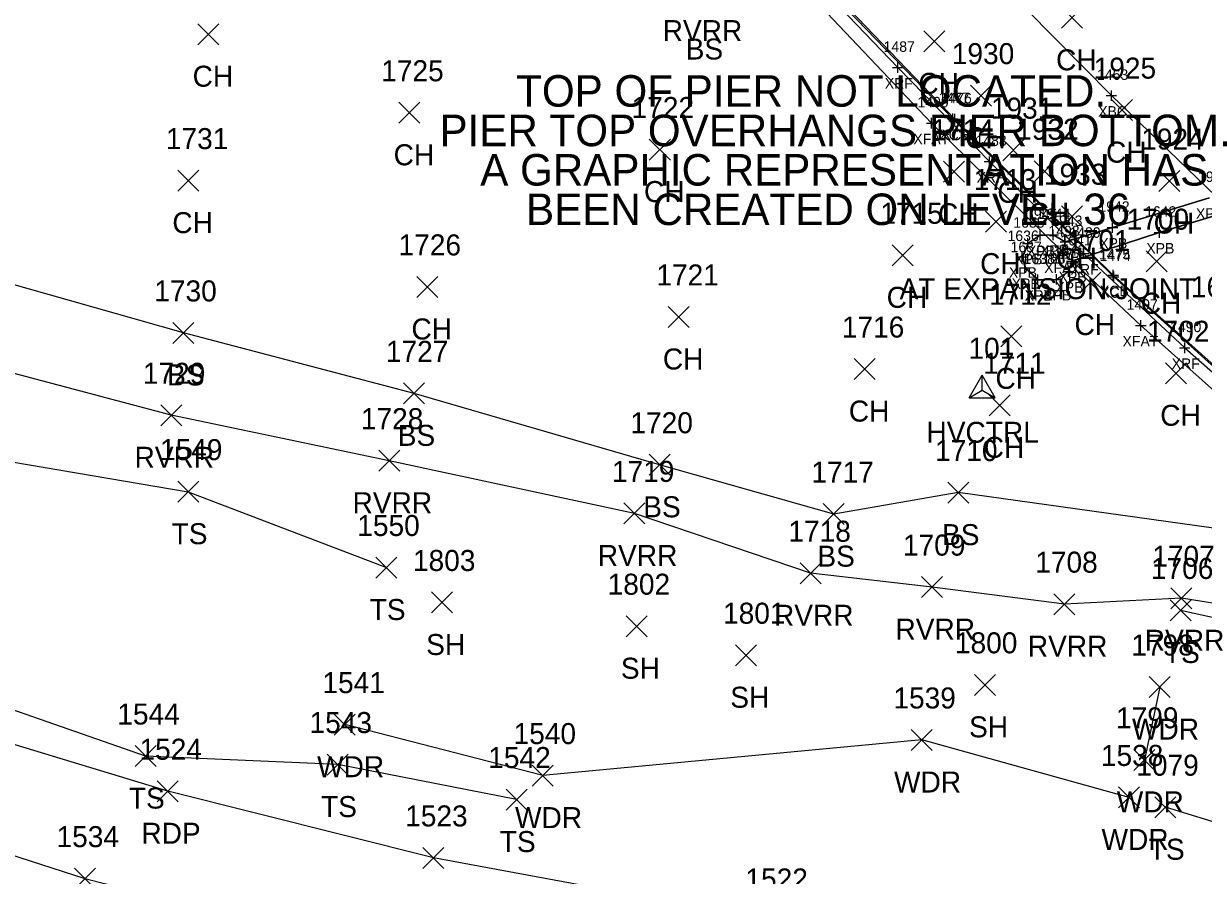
# Model space of a CAD drawing. Extents: x 1616726 to 1619875, y 273782 to 276557.
# Drawn here: x 1616883.5 to 1616995.8, y 276211.4 to 276292.5 of the extents above; entities that cross this region are included whole.
import ezdxf

# ---------------------------------------------------------------- set-up
doc = ezdxf.new("R2010")
doc.units = 0
for name, color, linetype in [('B_A', 7, 'Continuous'), ('B_C', 7, 'Continuous'), ('B_I', 7, 'Continuous'), ('B_TIC', 7, 'Continuous'), ('BDC', 7, 'Continuous'), ('BELB', 7, 'Continuous'), ('BF', 7, 'Continuous'), ('BR', 7, 'Continuous'), ('BSUBM', 7, 'Continuous'), ('C_A', 7, 'Continuous'), ('C_I', 7, 'Continuous'), ('CPSM', 7, 'Continuous'), ('L_A', 7, 'Continuous'), ('L_I', 7, 'Continuous'), ('L_TIC', 7, 'Continuous'), ('LAWA', 7, 'Continuous'), ('LAWE', 7, 'Continuous'), ('LELB', 7, 'Continuous'), ('Level 36', 7, 'Continuous'), ('P_A', 7, 'Continuous'), ('P_I', 7, 'Continuous'), ('P_TIC', 7, 'Continuous'), ('PET', 7, 'Continuous'), ('PRC', 7, 'Continuous')]:
    doc.layers.add(name, color=color, linetype=linetype)

msp = doc.modelspace()

# ---------------------------------------------------------------- linework, layer by layer
at = {"layer": 'B_TIC'}
for p, q in [((1616966.71, 276288.28), (1616966.79, 276288.28)), ((1616987.05, 276285.61), (1616987.13, 276285.61)), ((1616969.94, 276282.99), (1616970.01, 276282.99)), ((1616971.94, 276283.4), (1616972.02, 276283.4)), ((1616972.16, 276283.37), (1616972.23, 276283.37)), ((1616975.45, 276279.33), (1616975.53, 276279.33)), ((1616987.16, 276273.05), (1616987.24, 276273.05)), ((1616980.27, 276272.32), (1616980.34, 276272.32)), ((1616981.51, 276272.36), (1616981.59, 276272.36)), ((1616982.67, 276271.7), (1616982.74, 276271.7)), ((1616991.63, 276272.58), (1616991.71, 276272.58)), ((1616979.08, 276271.54), (1616979.16, 276271.54)), ((1616982.4, 276270.73), (1616982.48, 276270.73)), ((1616984.4, 276270.58), (1616984.48, 276270.58)), ((1616978.56, 276270.27), (1616978.64, 276270.27)), ((1616983.29, 276269.85), (1616983.36, 276269.85)), ((1616978.82, 276269.21), (1616978.9, 276269.21)), ((1616982.98, 276268.87), (1616983.06, 276268.87)), ((1616987.22, 276268.52), (1616987.3, 276268.52)), ((1616987.28, 276268.37), (1616987.35, 276268.37)), ((1616980.06, 276268.09), (1616980.14, 276268.09)), ((1616981.83, 276268.12), (1616981.91, 276268.12)), ((1616989.85, 276263.73), (1616989.93, 276263.73)), ((1616994.04, 276261.6), (1616994.11, 276261.6))]:
    msp.add_line(p, q, dxfattribs=at)
for points in [[(1616966.71, 276287.78), (1616966.71, 276288.78)], [(1616966.21, 276288.28), (1616967.21, 276288.28)], [(1616986.55, 276285.61), (1616987.55, 276285.61)], [(1616987.05, 276285.11), (1616987.05, 276286.11)], [(1616969.43, 276282.99), (1616970.43, 276282.99)], [(1616969.93, 276282.49), (1616969.93, 276283.49)], [(1616971.44, 276283.4), (1616972.44, 276283.4)], [(1616971.65, 276283.37), (1616972.65, 276283.37)], [(1616971.94, 276282.9), (1616971.94, 276283.9)], [(1616972.15, 276282.87), (1616972.15, 276283.87)], [(1616975.45, 276278.83), (1616975.45, 276279.83)], [(1616974.95, 276279.33), (1616975.95, 276279.33)], [(1616980.26, 276271.82), (1616980.26, 276272.82)], [(1616981.51, 276271.86), (1616981.51, 276272.86)], [(1616986.66, 276273.05), (1616987.66, 276273.05)], [(1616987.16, 276272.55), (1616987.16, 276273.55)], [(1616991.63, 276272.08), (1616991.63, 276273.08)], [(1616979.08, 276271.04), (1616979.08, 276272.04)], [(1616979.76, 276272.32), (1616980.76, 276272.32)], [(1616981.01, 276272.36), (1616982.01, 276272.36)], [(1616982.16, 276271.7), (1616983.16, 276271.7)], [(1616982.66, 276271.2), (1616982.66, 276272.2)], [(1616991.13, 276272.58), (1616992.13, 276272.58)], [(1616978.56, 276269.77), (1616978.56, 276270.77)], [(1616978.58, 276271.54), (1616979.58, 276271.54)], [(1616981.9, 276270.73), (1616982.9, 276270.73)], [(1616982.4, 276270.23), (1616982.4, 276271.23)], [(1616983.9, 276270.58), (1616984.9, 276270.58)], [(1616984.4, 276270.08), (1616984.4, 276271.08)], [(1616978.06, 276270.27), (1616979.06, 276270.27)], [(1616978.82, 276268.71), (1616978.82, 276269.71)], [(1616982.78, 276269.85), (1616983.78, 276269.85)], [(1616983.28, 276269.35), (1616983.28, 276270.35)], [(1616978.32, 276269.21), (1616979.32, 276269.21)], [(1616980.06, 276267.59), (1616980.06, 276268.59)], [(1616981.83, 276267.62), (1616981.83, 276268.62)], [(1616982.48, 276268.87), (1616983.48, 276268.87)], [(1616982.98, 276268.37), (1616982.98, 276269.37)], [(1616986.72, 276268.52), (1616987.72, 276268.52)], [(1616986.77, 276268.37), (1616987.77, 276268.37)], [(1616987.22, 276268.02), (1616987.22, 276269.02)], [(1616987.27, 276267.87), (1616987.27, 276268.87)], [(1616979.56, 276268.09), (1616980.56, 276268.09)], [(1616981.33, 276268.12), (1616982.33, 276268.12)], [(1616989.85, 276263.23), (1616989.85, 276264.23)], [(1616989.35, 276263.73), (1616990.35, 276263.73)], [(1616993.53, 276261.6), (1616994.53, 276261.6)], [(1616994.03, 276261.1), (1616994.03, 276262.1)]]:
    msp.add_lwpolyline(points, dxfattribs=at)
at = {"layer": 'BDC'}
for points in [[(1617031.94, 276230.49), (1617019.04, 276240.81), (1617003.31, 276253.92), (1616987.27, 276268.37), (1616971.94, 276283.4), (1616957.29, 276298.59), (1616946.1, 276311.24), (1616940.91, 276317.32)], [(1617032.09, 276230.63), (1617019.01, 276240.96), (1617003.45, 276254.01), (1616987.22, 276268.52), (1616972.15, 276283.37), (1616957.52, 276298.65), (1616946.38, 276311.13), (1616940.99, 276317.43)]]:
    msp.add_lwpolyline(points, dxfattribs=at)
at = {"layer": 'BELB'}
msp.add_lwpolyline([(1616953.62, 276321.31), (1616970.88, 276302.03), (1616987.05, 276285.61), (1616997.93, 276275.14), (1617015.41, 276259.54), (1617031.05, 276246.56), (1617046.39, 276234.45)], dxfattribs=at)
at = {"layer": 'BF'}
msp.add_lwpolyline([(1617030.01, 276230.06), (1617015.82, 276241.31), (1617001.54, 276253.31), (1616989.85, 276263.73), (1616982.4, 276270.73), (1616969.93, 276282.99), (1616958.21, 276295.37), (1616947.15, 276307.45), (1616939.12, 276316.79)], dxfattribs=at)
at = {"layer": 'BR'}
msp.add_lwpolyline([(1616940.54, 276317.17), (1616949.79, 276306.51), (1616958.1, 276297.28), (1616966.71, 276288.28), (1616975.45, 276279.33), (1616984.4, 276270.58), (1616994.03, 276261.6), (1617003.8, 276253.03), (1617019.44, 276239.96), (1617030.78, 276230.92)], dxfattribs=at)
at = {"layer": 'BSUBM'}
for points in [[(1616979.08, 276271.54), (1616978.56, 276270.27), (1616978.82, 276269.21), (1616980.06, 276268.09), (1616981.83, 276268.12), (1616982.98, 276268.87), (1616983.28, 276269.85), (1616991.63, 276272.58), (1617007.14, 276277.28)], [(1616996.36, 276275.89), (1616987.16, 276273.05), (1616982.66, 276271.7), (1616981.51, 276272.36), (1616980.26, 276272.32)], [(1616980.26, 276272.32), (1616979.08, 276271.54)]]:
    msp.add_lwpolyline(points, dxfattribs=at)
at = {"layer": 'CPSM'}
for p, q in [((1616973.49, 276256.84), (1616974.74, 276259)), ((1616973.49, 276256.84), (1616974.74, 276259)), ((1616973.49, 276256.84), (1616974.74, 276259)), ((1616975.99, 276256.84), (1616974.74, 276259)), ((1616974.74, 276257.56), (1616974.74, 276259)), ((1616975.99, 276256.84), (1616974.74, 276259)), ((1616974.74, 276257.56), (1616974.74, 276259)), ((1616975.99, 276256.84), (1616974.74, 276259)), ((1616974.74, 276257.56), (1616974.74, 276259)), ((1616973.49, 276256.84), (1616974.74, 276257.56)), ((1616973.49, 276256.84), (1616974.74, 276257.56)), ((1616973.49, 276256.84), (1616974.74, 276257.56)), ((1616974.74, 276257.56), (1616974.74, 276257.56)), ((1616974.74, 276257.56), (1616975.99, 276256.84)), ((1616974.74, 276257.56), (1616974.74, 276257.56)), ((1616974.74, 276257.56), (1616975.99, 276256.84)), ((1616974.74, 276257.56), (1616974.74, 276257.56)), ((1616974.74, 276257.56), (1616975.99, 276256.84)), ((1616973.49, 276256.84), (1616975.99, 276256.84)), ((1616973.49, 276256.84), (1616975.99, 276256.84)), ((1616973.49, 276256.84), (1616975.99, 276256.84))]:
    msp.add_line(p, q, dxfattribs=at)
at = {"layer": 'L_TIC'}
for points in [[(1616982.29, 276292.02), (1616984.29, 276294.02)], [(1616984.29, 276292.02), (1616982.29, 276294.02)], [(1616900.07, 276290.46), (1616902.07, 276292.46)], [(1616902.07, 276290.46), (1616900.07, 276292.46)], [(1616969.18, 276289.78), (1616971.18, 276291.78)], [(1616971.18, 276289.78), (1616969.18, 276291.78)], [(1616973.63, 276284.61), (1616975.63, 276286.61)], [(1616975.63, 276284.61), (1616973.63, 276286.61)], [(1616987.05, 276283.23), (1616989.05, 276285.23)], [(1616989.05, 276283.23), (1616987.05, 276285.23)], [(1616919.21, 276282.98), (1616921.21, 276284.98)], [(1616921.21, 276282.98), (1616919.21, 276284.98)], [(1616943.05, 276279.48), (1616945.05, 276281.48)], [(1616945.05, 276279.48), (1616943.05, 276281.48)], [(1616976.7, 276279.42), (1616978.7, 276281.42)], [(1616978.7, 276279.42), (1616976.7, 276281.42)], [(1616898.14, 276276.52), (1616900.14, 276278.52)], [(1616900.14, 276276.52), (1616898.14, 276278.52)], [(1616971.05, 276277.36), (1616973.05, 276279.36)], [(1616973.05, 276277.36), (1616971.05, 276279.36)], [(1616979.68, 276277.41), (1616981.68, 276279.41)], [(1616981.68, 276277.41), (1616979.68, 276279.41)], [(1616991.58, 276276.48), (1616993.58, 276278.48)], [(1616993.58, 276276.48), (1616991.58, 276278.48)], [(1616982.31, 276273.13), (1616984.31, 276275.13)], [(1616984.31, 276273.13), (1616982.31, 276275.13)], [(1616975.06, 276272.62), (1616977.06, 276274.62)], [(1616977.06, 276272.62), (1616975.06, 276274.62)], [(1616966.16, 276269.41), (1616968.16, 276271.41)], [(1616968.16, 276269.41), (1616966.16, 276271.41)], [(1616990.35, 276268.85), (1616992.35, 276270.85)], [(1616992.35, 276268.85), (1616990.35, 276270.85)], [(1616920.91, 276266.4), (1616922.91, 276268.4)], [(1616922.91, 276266.4), (1616920.91, 276268.4)], [(1616984.05, 276266.82), (1616986.05, 276268.82)], [(1616986.05, 276266.82), (1616984.05, 276268.82)], [(1616944.85, 276263.54), (1616946.85, 276265.54)], [(1616946.85, 276263.54), (1616944.85, 276265.54)], [(1616897.69, 276262.02), (1616899.69, 276264.02)], [(1616899.69, 276262.02), (1616897.69, 276264.02)], [(1616976.52, 276261.7), (1616978.52, 276263.7)], [(1616978.52, 276261.7), (1616976.52, 276263.7)], [(1616962.56, 276258.58), (1616964.56, 276260.58)], [(1616964.56, 276258.58), (1616962.56, 276260.58)], [(1616992.21, 276258.18), (1616994.21, 276260.18)], [(1616994.21, 276258.18), (1616992.21, 276260.18)], [(1616919.65, 276256.27), (1616921.65, 276258.27)], [(1616921.65, 276256.27), (1616919.65, 276258.27)], [(1616975.4, 276255.13), (1616977.4, 276257.13)], [(1616977.4, 276255.13), (1616975.4, 276257.13)], [(1616896.52, 276254.18), (1616898.52, 276256.18)], [(1616898.52, 276254.18), (1616896.52, 276256.18)], [(1616917.28, 276249.86), (1616919.28, 276251.86)], [(1616919.28, 276249.86), (1616917.28, 276251.86)], [(1616943.03, 276249.47), (1616945.03, 276251.47)], [(1616945.03, 276249.47), (1616943.03, 276251.47)], [(1616898.15, 276246.91), (1616900.15, 276248.91)], [(1616900.15, 276246.91), (1616898.15, 276248.91)], [(1616971.47, 276246.82), (1616973.47, 276248.82)], [(1616973.47, 276246.82), (1616971.47, 276248.82)], [(1616940.63, 276244.84), (1616942.63, 276246.84)], [(1616942.63, 276244.84), (1616940.63, 276246.84)], [(1616959.61, 276244.77), (1616961.61, 276246.77)], [(1616961.61, 276244.77), (1616959.61, 276246.77)], [(1616917.01, 276239.69), (1616919.01, 276241.69)], [(1616919.01, 276239.69), (1616917.01, 276241.69)], [(1616957.41, 276239.14), (1616959.41, 276241.14)], [(1616959.41, 276239.14), (1616957.41, 276241.14)], [(1616968.98, 276237.82), (1616970.98, 276239.82)], [(1616970.98, 276237.82), (1616968.98, 276239.82)], [(1616922.31, 276236.36), (1616924.31, 276238.36)], [(1616924.31, 276236.36), (1616922.31, 276238.36)], [(1616981.58, 276236.2), (1616983.58, 276238.2)], [(1616983.58, 276236.2), (1616981.58, 276238.2)], [(1616992.71, 276236.76), (1616994.71, 276238.76)], [(1616994.71, 276236.76), (1616992.71, 276238.76)], [(1616992.64, 276235.6), (1616994.64, 276237.6)], [(1616994.64, 276235.6), (1616992.64, 276237.6)], [(1616940.85, 276234.1), (1616942.85, 276236.1)], [(1616942.85, 276234.1), (1616940.85, 276236.1)], [(1616951.27, 276231.34), (1616953.27, 276233.34)], [(1616953.27, 276231.34), (1616951.27, 276233.34)], [(1616974.01, 276228.52), (1616976.01, 276230.52)], [(1616976.01, 276228.52), (1616974.01, 276230.52)], [(1616990.65, 276228.31), (1616992.65, 276230.31)], [(1616992.65, 276228.31), (1616990.65, 276230.31)], [(1616913.05, 276224.73), (1616915.05, 276226.73)], [(1616915.05, 276224.73), (1616913.05, 276226.73)], [(1616967.99, 276223.27), (1616969.99, 276225.27)], [(1616969.99, 276223.27), (1616967.99, 276225.27)], [(1616894.08, 276221.74), (1616896.08, 276223.74)], [(1616896.08, 276221.74), (1616894.08, 276223.74)], [(1616989.19, 276221.38), (1616991.19, 276223.38)], [(1616991.19, 276221.38), (1616989.19, 276223.38)], [(1616912.38, 276220.93), (1616914.38, 276222.93)], [(1616914.38, 276220.93), (1616912.38, 276222.93)], [(1616931.9, 276219.88), (1616933.9, 276221.88)], [(1616933.9, 276219.88), (1616931.9, 276221.88)], [(1616929.41, 276217.6), (1616931.41, 276219.6)], [(1616931.41, 276217.6), (1616929.41, 276219.6)], [(1616987.74, 276217.8), (1616989.74, 276219.8)], [(1616989.74, 276217.8), (1616987.74, 276219.8)], [(1616991.2, 276216.87), (1616993.2, 276218.87)], [(1616993.2, 276216.87), (1616991.2, 276218.87)]]:
    msp.add_lwpolyline(points, dxfattribs=at)
at = {"layer": 'LAWA'}
for points in [[(1616991.65, 276229.31), (1616990.19, 276222.38)], [(1616988.74, 276218.8), (1616968.99, 276224.27), (1616932.9, 276220.88), (1616914.05, 276225.73)]]:
    msp.add_lwpolyline(points, dxfattribs=at)
at = {"layer": 'LAWE'}
msp.add_lwpolyline([(1617025.7, 276233.23), (1617015.62, 276235.97), (1617001.8, 276236.48), (1616993.71, 276237.76), (1616982.58, 276237.2), (1616969.98, 276238.82), (1616958.41, 276240.14), (1616941.63, 276245.84), (1616918.28, 276250.86), (1616897.52, 276255.18), (1616867.23, 276263.21), (1616844.35, 276269.71), (1616814.42, 276281.91), (1616791.45, 276293.2)], dxfattribs=at)
at = {"layer": 'LELB'}
for points in [[(1617180.33, 276288.33), (1617161.43, 276281.85), (1617137.1, 276278.45), (1617120.41, 276268.03), (1617108.3, 276262.95), (1617094.24, 276258.02), (1617079.48, 276248.1), (1617068.22, 276247.78), (1617049.15, 276245.5), (1617035.06, 276240.81), (1617026.01, 276236.23), (1617014.97, 276241.9), (1616972.47, 276247.82), (1616960.61, 276245.77), (1616944.03, 276250.47), (1616920.65, 276257.27), (1616898.69, 276263.02), (1616845.5, 276278.09), (1616816.83, 276290.56), (1616792.38, 276296.23)], [(1616930.41, 276218.6), (1616913.38, 276221.93), (1616895.08, 276222.74), (1616874.95, 276229.74), (1616861.69, 276233.4), (1616870.25, 276244.59), (1616877.85, 276251.51), (1616899.15, 276247.91), (1616918.01, 276240.69)], [(1617014.97, 276234.39), (1617001.71, 276234.82), (1616993.64, 276236.6)], [(1617009.81, 276212.46), (1616992.2, 276217.87)]]:
    msp.add_lwpolyline(points, dxfattribs=at)
at = {"layer": 'Level 36'}
for points in [[(1616979.12, 276271.52), (1616978.61, 276270.27), (1616978.86, 276269.25), (1616980.09, 276268.12), (1616981.82, 276268.15), (1616982.96, 276268.88), (1616983.27, 276269.87), (1616991.63, 276272.61), (1617007.13, 276277.3)], [(1616996.37, 276275.86), (1616987.16, 276273.02), (1616982.65, 276271.67), (1616981.49, 276272.32), (1616980.27, 276272.3), (1616979.12, 276271.52)]]:
    msp.add_lwpolyline(points, dxfattribs=at)
at = {"layer": 'P_TIC'}
for points in [[(1616896.19, 276218.39), (1616898.19, 276220.39)], [(1616898.19, 276218.39), (1616896.19, 276220.39)], [(1616921.49, 276212.04), (1616923.49, 276214.04)], [(1616923.49, 276212.04), (1616921.49, 276214.04)], [(1616888.3, 276210.07), (1616890.3, 276212.07)], [(1616890.3, 276210.07), (1616888.3, 276212.07)]]:
    msp.add_lwpolyline(points, dxfattribs=at)
at = {"layer": 'PET'}
msp.add_lwpolyline([(1616988.41, 276201.28), (1616954.9, 276207.04), (1616922.49, 276213.04), (1616897.19, 276219.39), (1616868.83, 276227.99), (1616843.51, 276236.97), (1616821.5, 276246.17), (1616797.48, 276256.89), (1616777.93, 276266.16)], dxfattribs=at)
at = {"layer": 'PRC'}
msp.add_lwpolyline([(1616773.7, 276256.44), (1616798, 276244.91), (1616831.43, 276231.02), (1616858.04, 276221.16), (1616889.3, 276211.07), (1616917.92, 276203.82), (1616952.65, 276196.97), (1616987.1, 276190.69)], dxfattribs=at)

# ---------------------------------------------------------------- texts
at = {"layer": 'B_A'}
for s, p in [('XRF', (1616965.47, 276286.28)), ('XBC', (1616985.79, 276283.61)), ('XFAT', (1616968.19, 276280.99)), ('XCT', (1616970.66, 276281.4)), ('XCB', (1616970.89, 276281.37)), ('XRF', (1616974.21, 276277.33)), ('XPB', (1616995.1, 276273.89)), ('XPB', (1616985.89, 276271.05)), ('XPB', (1616979, 276270.32)), ('XPB', (1616980.24, 276270.36)), ('XPB', (1616981.4, 276269.7)), ('XPB', (1616990.37, 276270.58)), ('XPB', (1616977.82, 276269.54)), ('XFAT', (1616980.65, 276268.73)), ('XRF', (1616983.16, 276268.58)), ('XPB', (1616977.29, 276268.27)), ('XPB', (1616982.02, 276267.85)), ('XPB', (1616977.55, 276267.21)), ('XPB', (1616981.71, 276266.87)), ('XCB', (1616985.95, 276266.52)), ('XCT', (1616985.99, 276266.37)), ('XPB', (1616978.79, 276266.09)), ('XPB', (1616980.56, 276266.12)), ('XFAT', (1616988.11, 276261.73)), ('XRF', (1616992.79, 276259.6))]:
    msp.add_text(s, height=1, dxfattribs=at).set_placement(p)
at = {"layer": 'B_C'}
for s, height, p in [('TOP OF PIER NOT LOCATED.  ', 3, (1616930.37, 276284.56)), ('PIER TOP OVERHANGS PIER BOTTOM.', 3, (1616923.07, 276280.8)), ('A GRAPHIC REPRESENTATION HAS', 3, (1616926.95, 276277.05)), ('BEEN CREATED ON LEVEL 36', 3, (1616931.31, 276273.29)), ('AT EXPANSION JOINT', 2, (1616966.88, 276266.23))]:
    msp.add_text(s, height=height, dxfattribs=at).set_placement(p)
at = {"layer": 'B_I'}
for s, p in [('1487', (1616965.36, 276289.78)), ('1463', (1616985.68, 276287.11)), ('1499', (1616968.58, 276284.49)), ('1477', (1616970.59, 276284.9)), ('1476', (1616970.78, 276284.87)), ('1488', (1616974.1, 276280.83)), ('1941', (1616995.3, 276277.39)), ('1942', (1616985.81, 276274.55)), ('1642', (1616990.26, 276274.08)), ('1635', (1616977.71, 276273.04)), ('1945', (1616978.92, 276273.82)), ('1944', (1616980.16, 276273.86)), ('1943', (1616981.32, 276273.2)), ('1498', (1616981.05, 276272.23)), ('1489', (1616983.05, 276272.08)), ('1636', (1616977.16, 276271.77)), ('1637', (1616977.45, 276270.71)), ('1641', (1616982.2, 276271.35)), ('1638', (1616978.69, 276269.59)), ('1639', (1616980.45, 276269.62)), ('1640', (1616981.56, 276270.37)), ('1475', (1616985.87, 276270.02)), ('1474', (1616985.93, 276269.87)), ('1497', (1616988.5, 276265.23)), ('1490', (1616992.64, 276263.1))]:
    msp.add_text(s, height=1, dxfattribs=at).set_placement(p)
at = {"layer": 'C_A'}
msp.add_text('HVCTRL', height=2, dxfattribs=at).set_placement((1616969.44, 276252.56))
msp.add_text('HVCTRL', height=2, dxfattribs=at).set_placement((1616969.44, 276252.56))
msp.add_text('HVCTRL', height=2, dxfattribs=at).set_placement((1616969.44, 276252.56))
at = {"layer": 'C_I'}
msp.add_text('101', height=2, dxfattribs=at).set_placement((1616973.44, 276260.56))
msp.add_text('101', height=2, dxfattribs=at).set_placement((1616973.44, 276260.56))
msp.add_text('101', height=2, dxfattribs=at).set_placement((1616973.44, 276260.56))
at = {"layer": 'L_A'}
for s, p in [('RVRR', (1616944.32, 276290.8)), ('BS', (1616946.51, 276289.05)), ('CH', (1616981.78, 276288.02)), ('CH', (1616899.56, 276286.46)), ('CH', (1616968.67, 276285.78)), ('CH', (1616973.12, 276280.61)), ('CH', (1616918.7, 276278.98)), ('CH', (1616986.54, 276279.23)), ('CH', (1616942.54, 276275.48)), ('CH', (1616976.19, 276275.42)), ('CH', (1616970.54, 276273.36)), ('CH', (1616979.17, 276273.41)), ('CH', (1616897.63, 276272.52)), ('CH', (1616991.07, 276272.48)), ('CH', (1616974.55, 276268.62)), ('CH', (1616981.8, 276269.13)), ('CH', (1616965.65, 276265.41)), ('CH', (1616989.84, 276264.85)), ('CH', (1616920.4, 276262.4)), ('CH', (1616983.54, 276262.82)), ('CH', (1616944.34, 276259.54)), ('BS', (1616897.13, 276258.02)), ('CH', (1616976.01, 276257.7)), ('CH', (1616962.05, 276254.58)), ('CH', (1616991.7, 276254.18)), ('BS', (1616919.09, 276252.27)), ('CH', (1616974.89, 276251.13)), ('RVRR', (1616894.03, 276250.18)), ('RVRR', (1616914.79, 276245.86)), ('BS', (1616942.47, 276245.47)), ('TS', (1616897.56, 276242.91)), ('BS', (1616970.92, 276242.82)), ('RVRR', (1616938.14, 276240.84)), ('BS', (1616959.05, 276240.77)), ('TS', (1616916.42, 276235.69)), ('RVRR', (1616954.92, 276235.14)), ('RVRR', (1616966.49, 276233.82)), ('RVRR', (1616990.23, 276232.76)), ('SH', (1616921.8, 276232.36)), ('RVRR', (1616979.09, 276232.2)), ('TS', (1616992.05, 276231.6)), ('SH', (1616940.34, 276230.1)), ('SH', (1616950.76, 276227.34)), ('SH', (1616973.5, 276224.52)), ('WDR', (1616989.01, 276224.31)), ('WDR', (1616911.41, 276220.73)), ('WDR', (1616966.35, 276219.27)), ('TS', (1616893.49, 276217.74)), ('TS', (1616911.79, 276216.93)), ('WDR', (1616987.56, 276217.38)), ('WDR', (1616930.26, 276215.88)), ('TS', (1616928.81, 276213.6)), ('WDR', (1616986.11, 276213.8)), ('TS', (1616990.61, 276212.87))]:
    msp.add_text(s, height=2, dxfattribs=at).set_placement(p)
at = {"layer": 'L_I'}
for s, p in [('1930', (1616971.85, 276288.61)), ('1725', (1616917.52, 276286.98)), ('1925', (1616985.36, 276287.23)), ('1722', (1616941.36, 276283.48)), ('1931', (1616975.57, 276283.42)), ('1714', (1616969.92, 276281.36)), ('1932', (1616977.98, 276281.41)), ('1731', (1616897.01, 276280.52)), ('1924', (1616989.89, 276280.48)), ('1713', (1616973.94, 276276.62)), ('1933', (1616980.62, 276277.13)), ('1715', (1616965.04, 276273.41)), ('1700', (1616988.5, 276272.85)), ('1701', (1616982.84, 276270.82)), ('1726', (1616919.17, 276270.4)), ('1721', (1616943.72, 276267.54)), ('1699', (1616994.62, 276266.42)), ('1730', (1616895.91, 276266.02)), ('1712', (1616975.4, 276265.7)), ('1716', (1616961.38, 276262.58)), ('1702', (1616990.44, 276262.18)), ('1727', (1616917.96, 276260.27)), ('1711', (1616974.84, 276259.13)), ('1729', (1616894.82, 276258.18)), ('1728', (1616915.58, 276253.86)), ('1720', (1616941.25, 276253.47)), ('1549', (1616896.45, 276250.91)), ('1710', (1616970.26, 276250.82)), ('1719', (1616939.49, 276248.84)), ('1717', (1616958.48, 276248.77)), ('1550', (1616915.24, 276243.69)), ('1718', (1616956.29, 276243.14)), ('1709', (1616967.2, 276241.82)), ('1707', (1616990.94, 276240.76)), ('1803', (1616920.54, 276240.36)), ('1708', (1616979.8, 276240.2)), ('1706', (1616990.81, 276239.6)), ('1802', (1616939.08, 276238.1)), ('1801', (1616950.07, 276235.34)), ('1800', (1616972.15, 276232.52)), ('1798', (1616988.95, 276232.31)), ('1541', (1616911.92, 276228.73)), ('1539', (1616966.29, 276227.27)), ('1544', (1616892.39, 276225.74)), ('1543', (1616910.69, 276224.93)), ('1799', (1616987.49, 276225.38)), ('1540', (1616930.12, 276223.88)), ('1542', (1616927.71, 276221.6)), ('1538', (1616986.05, 276221.8)), ('1079', (1616989.42, 276220.87))]:
    msp.add_text(s, height=2, dxfattribs=at).set_placement(p)
at = {"layer": 'P_A'}
msp.add_text('RDP', height=2, dxfattribs=at).set_placement((1616894.68, 276214.39))
at = {"layer": 'P_I'}
for s, p in [('1524', (1616894.5, 276222.39)), ('1523', (1616919.8, 276216.04)), ('1534', (1616886.6, 276214.07)), ('1522', (1616952.2, 276210.04))]:
    msp.add_text(s, height=2, dxfattribs=at).set_placement(p)

doc.saveas('drawing.dxf')
